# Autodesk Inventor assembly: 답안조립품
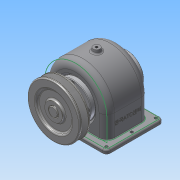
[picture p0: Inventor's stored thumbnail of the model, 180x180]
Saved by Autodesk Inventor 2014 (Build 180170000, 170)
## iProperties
Created: 2015-09
Part Number: 답안조립품
Document SubType Name: Assembly
Designer: sda1
Author: sda1
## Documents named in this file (14)
- C:\Users\sda1\Desktop\450907V1016\답안조립품.iam
- C:\Users\sda1\Desktop\450907V1016\본체.ipt
- C:\Users\sda1\Desktop\450907V1016\축.ipt
- C:\Users\sda1\Desktop\450907V1016\베어링 6203.ipt
- C:\Users\sda1\Desktop\450907V1016\키 - 6 x 6 x 22.ipt
- C:\Users\sda1\Desktop\450907V1016\스퍼기어.ipt
- C:\Users\sda1\Desktop\450907V1016\앞커버.ipt
- C:\Users\sda1\Desktop\450907V1016\오일 실 17 32 8.ipt
- C:\Users\sda1\Desktop\450907V1016\키 - 5 x 5 x 18.ipt
- C:\Users\sda1\Desktop\450907V1016\V-벨트풀리.ipt
- C:\Users\sda1\Desktop\450907V1016\멈춤나사 - M4x10.ipt
- C:\Users\sda1\Desktop\450907V1016\뒤커버.ipt
- C:\Users\sda1\Desktop\450907V1016\볼트 M3 x 10.ipt
- C:\Users\sda1\Desktop\450907V1016\볼트 M3 x 8.ipt
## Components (9 placed, 3 different names)
1. V-벨트풀리:1 — 각도:4
2. ISO 4762 M3 x 10:1
3. ISO 4762 M3 x 10:2
4. ISO 4762 M3 x 10:3
5. ISO 4762 M3 x 10:4
6. ISO 4762 M3 x 8:1
7. ISO 4762 M3 x 8:2
8. ISO 4762 M3 x 8:3
9. ISO 4762 M3 x 8:4
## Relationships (1: Angle 1)
- 각도:4 [Angle]: V-벨트풀리:1
